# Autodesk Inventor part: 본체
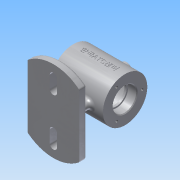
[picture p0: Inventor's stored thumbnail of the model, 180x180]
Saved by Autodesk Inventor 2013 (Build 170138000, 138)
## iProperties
Created: 2017-12
Part Number: 본체
Material: 알루미늄 6061
Document SubType Name: Modeling
Designer: Administrator
Density: 2.71 g/cm^3
Mass: 467.728 g
Surface Area: 486.608 cm^2
Volume: 172.593 cm^3
Author: Administrator
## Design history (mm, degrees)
sketch "스케치1"
  geometry: L1 (-35, 16)-(-23, 16); L2 (-23, 16)-(-23, 14); L3 (-23, 14)-(-20, 14); L4 (-20, 14)-(-20, 25); L5 (-20, 25)-(20, 25); L6 (20, 25)-(20, 14); L7 (20, 14)-(23, 14); L8 (23, 14)-(23, 16); L9 (23, 16)-(35, 16); L10 (35, 16)-(35, 30); L11 (35, 30)-(-35, 30); L12 (-35, 30)-(-35, 16); L13 (-49, 0)-(49, 0) reference; 1 further point
  constraints: 24 end point, 9 parallel, 1 collinear, 1 horizontal, 1 perpendicular
  dimensions: "d0" = 16 distance from line of L1 point (0, 0); "d1" = 14 distance from line of L3 point (0, 0); "d2" = 25 distance from line of L5 point (0, 0); "d3" = 14 distance from line of L7 point (0, 0); "d4" = 16 distance from line of L9 point (0, 0); "d5" = 70 distance of L10.end L11.end; "d6" = 12 distance of L1.start L1.end; "d7" = 3 distance of L2.end L3.end; "d8" = 40 distance of L4.end L5.end; "d9" = 3 distance of L6.end L7.end; "d10" = 30 distance from line of L11 point (0, 0); "d11" = 35 distance from line of L12 point (0, 0)
revolve "회전1" sketch "스케치1" stored, may be unused: angle "d12" = 90 deg
sketch "스케치2"
  geometry: C1 r 30 at (0, 0) reference; 1 further point
  constraints: 1 vertical alignment
  dimensions: "d13" = 23 distance of point (0, 23) C1.centre
hole "구멍1" sketch "스케치2" at (0, 23) diameter "d14" = 3.242; stored, may be unused: countersink angle "d18" = 90 deg, drill point angle "d20" = 118 deg; dims "d15" = 8, "d16" = 4, "d17" = 2, "d19" = 10
node "작업 평면1"
sketch "스케치3"
  geometry: C1 r 8 at (0, 0); 1 further point
  constraints: 1 centre point, 1 coincident
  dimensions: "d25" = 16 diameter of C1
extrude "돌출1" join sketch "스케치3" stored distance "d27" = 10; taper "d28" = 0 deg
hole "구멍2" diameter "d31" = 8; stored, may be unused: countersink angle "d35" = 90 deg, drill point angle "d37" = 118 deg; dims "d29" = 10, "d30" = 10, "d32" = 8, "d33" = 4, "d34" = 2, "d36" = 20
node "작업 평면2"
sketch "스케치4"
  geometry: L1 (35, 42.426)-(35, -42.426); L2 (-35, -42.426)-(-35, 42.426); C1 r 55 at (0, 0); A1 r 55 centre (0, 0) between (35, 42.426) and (-35, 42.426); A2 r 55 centre (0, 0) between (-35, -42.426) and (35, -42.426); 1 further point
  constraints: 4 end point, 4 point on circle, 3 centre point, 2 coincident, 1 parallel, 1 vertical
  dimensions: "d41" = 35 distance from line of L2 point (0, 0); "d42" = 70 distance between parallel lines of L1 L2; "d43" = 55 radius of A1; "d44" = 55 radius of A2; "d45" = 110 diameter of C1
extrude "돌출2" join sketch "스케치4" distance "d46" = 10; taper "d47" = 0 deg
sketch "스케치5"
  geometry: L1 (5, 40)-(5, 24); L2 (-5, 24)-(-5, 40); A1 r 55 centre (0, 0) between (-35, -42.426) and (35, -42.426) reference; A2 r 5 centre (0, 40) between (5, 40) and (-5, 40); A3 r 5 centre (0, 24) between (-5, 24) and (5, 24)
  constraints: 4 end point, 4 point on circle, 2 centre point, 2 tangent, 1 parallel, 1 vertical alignment
  dimensions: "d48" = 5 distance from line of L2 A1.centre; "d49" = 10 distance of L1.end L2.start; "d52" = 10 diameter of A2; "d53" = 10 diameter of A3; "d54" = 16 distance of A3.centre A2.centre; "d55" = 24 distance of A1.centre A3.centre
extrude "돌출3" cut sketch "스케치5" stored distance "d56" = 0; taper "d57" = 0 deg
sketch "스케치6"
  geometry: L1 (-15, 5)-(15, 5); L2 (15, -5)-(-15, -5); A1 r 55 centre (0, 0) between (-35, -42.426) and (35, -42.426) reference; A2 r 5 centre (-15, 0) between (-15, 5) and (-15, -5); A3 r 5 centre (15, 0) between (15, -5) and (15, 5)
  constraints: 4 end point, 4 point on circle, 2 centre point, 2 tangent, 1 horizontal, 1 parallel
  dimensions: "d61" = 10 distance of L2.end L1.start; "d62" = 5 distance from line of L1 A1.centre; "d63" = 10 diameter of A2; "d64" = 10 diameter of A3; "d65" = 30 distance of A2.centre A3.centre; "d66" = 15 distance of A2.centre A1.centre
extrude "돌출4" join sketch "스케치6" stored distance "d67" = 0; taper "d68" = 0 deg
chamfer "모따기1" distance "d69" = 1; stored, may be unused: second distance "d70" = 2, angle "d71" = 45 deg
fillet "모깎기1" dims "d72" = 5
fillet "모깎기2" dims "d73" = 3
fillet "모깎기3" dims "d74" = 0.3
node "작업 평면3"
sketch "스케치8"
  geometry: L1 (-26.203, 13.016)-(26.888, 13.016); L2 (26.888, 13.016)-(26.888, -12.673); L3 (26.888, -12.673)-(-26.203, -12.673); L4 (-26.203, -12.673)-(-26.203, 13.016); 1 further point
  constraints: 2 other
feature "엠보싱1" sketch "스케치8" dims "d0" = 16, "d1" = 14, "d2" = 25, "d3" = 14, "d4" = 16, "d5" = 70, "d6" = 12, "d7" = 3, "d8" = 40, "d9" = 3, "d10" = 30, "d11" = 35, "d76" = 0.5, "d77" = 0
node "솔리드1"
pattern_circular "원형 패턴1" dims angle "d22" = 360 deg
mirror "대칭1"
mirror "대칭2"
other parameters: "d24" = 37, "d38" = -62
